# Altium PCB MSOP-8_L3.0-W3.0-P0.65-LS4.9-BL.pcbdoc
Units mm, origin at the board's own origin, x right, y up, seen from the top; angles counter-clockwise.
Board outline 15.73 x 18.7 mm, 2 copper layers (Top Layer, Bottom Layer), stack 0.07 mm thick; 1 components, 0 nets, 8 pads, 0 vias.
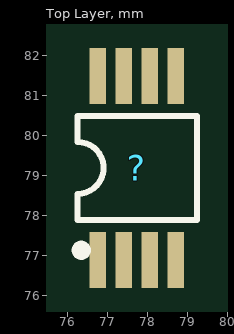
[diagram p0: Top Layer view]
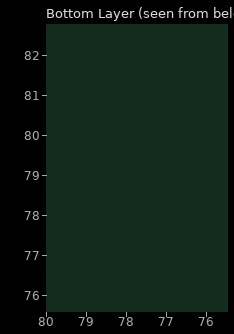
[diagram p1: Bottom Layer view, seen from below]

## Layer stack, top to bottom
Top Solder Mask Layer: solder mask 0.01, Dk 3.3
Top Layer: signal copper 0.035
Bottom Layer: signal copper 0.035
Bottom Solder Mask Layer: solder mask 0.01, Dk 3.3

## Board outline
85.58,69.85 69.85,69.85 69.85,88.547 85.58,88.547

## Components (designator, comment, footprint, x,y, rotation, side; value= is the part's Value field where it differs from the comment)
? "MSOP-8_L3.0-W3.0-P0.65-LS4.9-BL" MSOP-8_L3.0-W3.0-P0.65-LS4.9-BL 77.73,79.198 r0 top

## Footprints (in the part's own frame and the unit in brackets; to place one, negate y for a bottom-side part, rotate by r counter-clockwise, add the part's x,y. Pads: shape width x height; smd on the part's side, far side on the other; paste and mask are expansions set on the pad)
MSOP-8_L3.0-W3.0-P0.65-LS4.9-BL [mil]
  rect 15.98x55 smd paste+0 mask+2: 1(-38.39,-90.56) 2(-12.8,-90.56) 3(12.8,-90.55) 4(38.39,-90.55) 5(38.39,90.55) 6(12.8,90.56) 7(-12.8,90.55) 8(-38.39,90.55)
  silkscreen extent -59,-86 59,51

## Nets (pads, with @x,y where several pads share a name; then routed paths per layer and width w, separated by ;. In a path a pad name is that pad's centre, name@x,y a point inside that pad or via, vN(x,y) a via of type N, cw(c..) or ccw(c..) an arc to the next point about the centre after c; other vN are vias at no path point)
pads on no net: ?.1 ?.2 ?.3 ?.4 ?.5 ?.6 ?.7 ?.8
